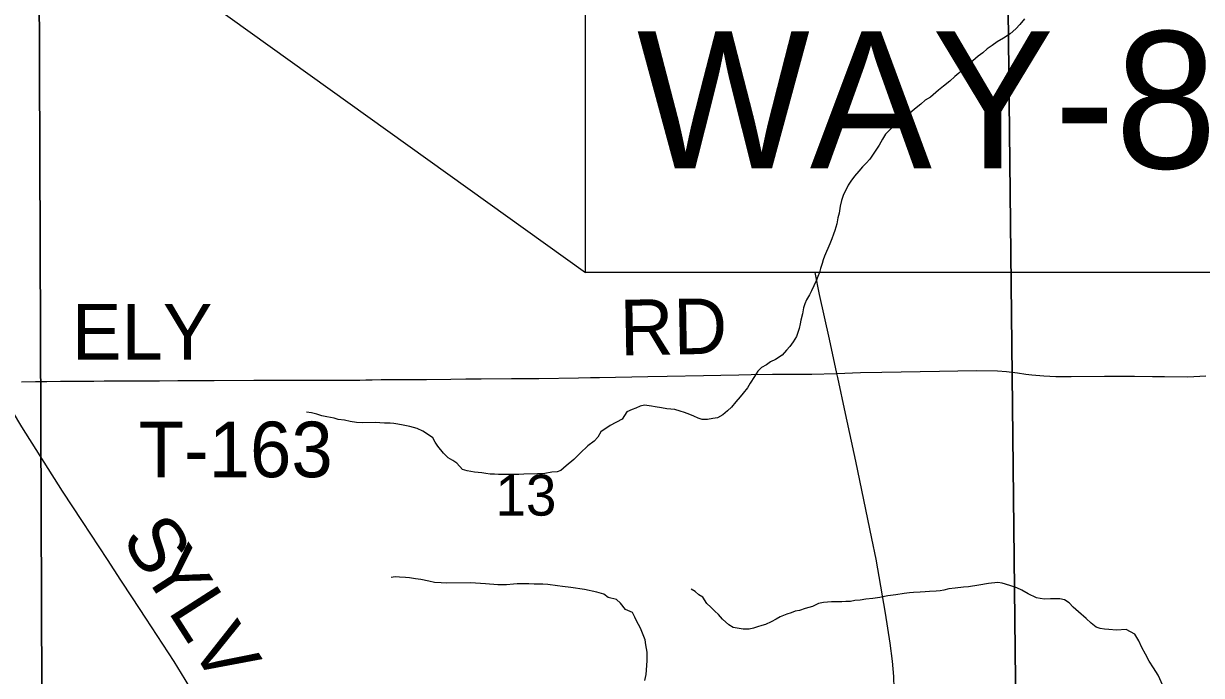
# Model space of a CAD drawing. Extents: x 0 to 34, y 0 to 22.
# Drawn here: x 22.282 to 23.486, y 11.815 to 12.481 of the extents above; entities that cross this region are included whole.
import ezdxf

# ---------------------------------------------------------------- set-up
doc = ezdxf.new("R2010")
doc.units = 0
for name, color, linetype in [('GM_X_County_Road', 7, 'Continuous'), ('GM_X_County_Road_Text', 7, 'Continuous'), ('GM_X_Minor_River', 7, 'Continuous'), ('GM_X_Section', 7, 'Continuous'), ('GM_X_Section_Text', 7, 'Continuous'), ('GM_X_Township_Road', 7, 'Continuous'), ('GM_X_Township_Road_Text', 7, 'Continuous'), ('SH_Text', 7, 'Continuous')]:
    doc.layers.add(name, color=color, linetype=linetype)

msp = doc.modelspace()

# ---------------------------------------------------------------- linework, layer by layer
at = {"layer": 'GM_X_County_Road'}
for points in [[(23.1137, 12.124), (23.106, 12.159), (23.096, 12.2046), (23.0913, 12.227)], [(22.5536, 11.616), (22.5355, 11.6502), (22.5139, 11.6915), (22.4919, 11.7326), (22.4757, 11.7627), (22.4634, 11.7843), (22.4475, 11.8111), (22.436, 11.8296), (22.4072, 11.8738), (22.3935, 11.8946), (22.3817, 11.9128), (22.3681, 11.9336), (22.3424, 11.9725), (22.3219, 12.0037), (22.2805, 12.0694), (22.2709, 12.0853), (22.2634, 12.0989), (22.2591, 12.1073), (22.2553, 12.1152)], [(23.1726, 11.6218), (23.1725, 11.6372), (23.1727, 11.69), (23.1722, 11.7304), (23.1721, 11.7677), (23.1722, 11.8019), (23.1717, 11.8143), (23.1704, 11.8297), (23.1681, 11.8482), (23.1633, 11.8789), (23.1585, 11.9065), (23.1536, 11.934), (23.1493, 11.9553), (23.1329, 12.0344), (23.1224, 12.0831), (23.1147, 12.1196), (23.1137, 12.124)]]:
    msp.add_lwpolyline(points, dxfattribs=at)
at = {"layer": 'GM_X_Minor_River'}
for points in [[(23.3053, 12.4863), (23.3008, 12.4806), (23.2967, 12.476), (23.2906, 12.471), (23.2839, 12.4667), (23.2774, 12.4628), (23.2722, 12.4589), (23.2673, 12.4555), (23.2628, 12.4516), (23.2579, 12.4481), (23.2526, 12.4435), (23.2481, 12.44), (23.2436, 12.4358), (23.2383, 12.4308), (23.2342, 12.4273), (23.2289, 12.4227), (23.2225, 12.4176), (23.2176, 12.4134), (23.2093, 12.4064), (23.204, 12.4033), (23.1995, 12.3991), (23.1931, 12.3941), (23.1879, 12.3894), (23.183, 12.3856), (23.1792, 12.3817), (23.1739, 12.3786), (23.1687, 12.374), (23.1634, 12.3686), (23.1601, 12.3632), (23.1567, 12.3571), (23.1508, 12.3479), (23.1474, 12.3429), (23.1437, 12.3387), (23.1399, 12.3349), (23.1362, 12.3306), (23.1317, 12.3256), (23.1279, 12.3203), (23.1253, 12.3164), (23.1201, 12.3057), (23.1183, 12.3008), (23.1168, 12.295), (23.1158, 12.2878), (23.1147, 12.2829), (23.1137, 12.2768), (23.1115, 12.2699), (23.11, 12.2661), (23.1085, 12.2615), (23.1063, 12.2562), (23.1011, 12.2439), (23.0997, 12.2401), (23.0986, 12.2363), (23.0967, 12.231), (23.0957, 12.2272), (23.0942, 12.223), (23.0923, 12.2184), (23.0901, 12.2134), (23.0875, 12.2084), (23.0857, 12.2042), (23.0827, 12.1992), (23.0809, 12.195), (23.0794, 12.1908), (23.0783, 12.1848), (23.0769, 12.1783), (23.0762, 12.1745), (23.0751, 12.1699), (23.0722, 12.1615), (23.0688, 12.1561), (23.0655, 12.1515), (23.0621, 12.1477), (23.0576, 12.1427), (23.0508, 12.138), (23.0459, 12.1357), (23.0417, 12.1326), (23.0364, 12.1299), (23.0327, 12.1264), (23.0293, 12.1207), (23.0249, 12.1141), (23.0223, 12.1092), (23.0178, 12.1038), (23.0148, 12.1), (23.0103, 12.095), (23.0058, 12.0896), (23.0017, 12.0857)], [(23.0017, 12.0857), (22.9971, 12.0815), (22.9915, 12.0784), (22.9869, 12.0779), (22.9812, 12.0767), (22.9759, 12.077), (22.9717, 12.0781), (22.9675, 12.0803), (22.9633, 12.0818), (22.9579, 12.084), (22.9534, 12.0855), (22.948, 12.0869), (22.9396, 12.0879), (22.9343, 12.0886), (22.9278, 12.0897), (22.924, 12.0904), (22.9171, 12.0914), (22.9126, 12.0906), (22.9081, 12.0883), (22.9043, 12.0871), (22.899, 12.0847), (22.8941, 12.0771), (22.882, 12.0708), (22.8722, 12.0643), (22.8693, 12.0589), (22.8655, 12.0547), (22.8591, 12.05), (22.8512, 12.0423), (22.8448, 12.0358), (22.8369, 12.0296), (22.8313, 12.0246), (22.8275, 12.0234), (22.8222, 12.0229), (22.815, 12.0217), (22.8074, 12.0212), (22.7937, 12.021), (22.7884, 12.0206), (22.78, 12.0205), (22.7716, 12.0207), (22.7678, 12.0207), (22.7636, 12.021), (22.7591, 12.021), (22.7549, 12.0217), (22.7507, 12.0224), (22.7431, 12.023), (22.7358, 12.0244), (22.7309, 12.0259), (22.7251, 12.0323), (22.7209, 12.0349), (22.7163, 12.0375), (22.7116, 12.0424), (22.7055, 12.0495), (22.7028, 12.0536), (22.7004, 12.0582), (22.695, 12.0619), (22.6904, 12.0649), (22.6847, 12.0675), (22.6771, 12.0696), (22.6702, 12.0711), (22.6649, 12.0721), (22.6607, 12.0728), (22.6569, 12.0732), (22.6512, 12.0731), (22.6462, 12.0734), (22.6416, 12.0737), (22.6287, 12.0735), (22.6226, 12.0738), (22.6161, 12.0749), (22.6104, 12.076), (22.6039, 12.077), (22.5997, 12.0781), (22.5921, 12.0795), (22.5872, 12.0806), (22.5818, 12.0824), (22.5765, 12.0835), (22.5715, 12.0842)], [(22.9174, 11.81), (22.9188, 11.8161), (22.9198, 11.8301), (22.9197, 11.8389), (22.9184, 11.8464), (22.9176, 11.8518), (22.9129, 11.8635), (22.9086, 11.871), (22.907, 11.8748), (22.9047, 11.8797), (22.8974, 11.8826), (22.8924, 11.889), (22.8882, 11.8928), (22.8798, 11.8949), (22.8752, 11.8983), (22.8683, 11.9005), (22.8557, 11.903), (22.8416, 11.9051), (22.8332, 11.9061), (22.8279, 11.9068), (22.818, 11.9082), (22.813, 11.9085), (22.8043, 11.9087), (22.7986, 11.909), (22.7868, 11.9089), (22.783, 11.9085), (22.7758, 11.908), (22.767, 11.9079), (22.7545, 11.9088), (22.7442, 11.9095), (22.7388, 11.9098), (22.7141, 11.9094), (22.7092, 11.9098), (22.7023, 11.9104), (22.6966, 11.9115), (22.6882, 11.9133), (22.6829, 11.914), (22.6768, 11.915), (22.6726, 11.9153), (22.6665, 11.9156), (22.6619, 11.916), (22.6581, 11.9155)], [(23.3993, 11.8616), (23.3917, 11.8622), (23.3871, 11.8626), (23.3826, 11.8633), (23.3787, 11.8647), (23.3734, 11.8688), (23.3684, 11.8733), (23.3607, 11.8801), (23.3553, 11.8849), (23.351, 11.8894), (23.3464, 11.8924), (23.3415, 11.8935), (23.3369, 11.8934), (23.332, 11.8937), (23.3259, 11.8933), (23.3213, 11.894), (23.3175, 11.8947), (23.3091, 11.8988), (23.3026, 11.9025), (23.2976, 11.9047), (23.2903, 11.9072), (23.2827, 11.9094), (23.2781, 11.9101), (23.2686, 11.9092), (23.2588, 11.9076), (23.2481, 11.9059), (23.2432, 11.9055), (23.2345, 11.9046), (23.228, 11.9038), (23.2231, 11.9025), (23.2193, 11.9017), (23.2151, 11.9013), (23.2083, 11.9012), (23.2037, 11.9008), (23.1988, 11.9003), (23.1919, 11.8999), (23.1878, 11.8998), (23.1824, 11.899), (23.1737, 11.8977), (23.1657, 11.8965), (23.1574, 11.8948), (23.1502, 11.894), (23.1433, 11.8931), (23.1373, 11.8923), (23.132, 11.8918), (23.1274, 11.891), (23.1228, 11.891), (23.1187, 11.8905), (23.108, 11.8904), (23.1, 11.8899), (23.0947, 11.8887), (23.0887, 11.8856), (23.0811, 11.8836), (23.0754, 11.8816), (23.0709, 11.8808), (23.0667, 11.8792), (23.0625, 11.878), (23.0557, 11.8752), (23.0516, 11.8729), (23.0463, 11.8702), (23.0406, 11.8674), (23.0368, 11.8663), (23.0323, 11.8651), (23.0285, 11.8635), (23.0239, 11.8627), (23.0179, 11.8626), (23.0137, 11.8633), (23.0076, 11.8644), (23.003, 11.8669), (22.9968, 11.8729), (22.9926, 11.8774), (22.9887, 11.8808), (22.9849, 11.8849), (22.9806, 11.8887), (22.9767, 11.8951), (22.9725, 11.8977), (22.9687, 11.9011), (22.9648, 11.9033)], [(23.4467, 11.8051), (23.4421, 11.8157), (23.4374, 11.8229), (23.4328, 11.8297), (23.429, 11.8369), (23.4255, 11.8437), (23.4224, 11.8505), (23.4181, 11.8574), (23.4094, 11.8621), (23.3993, 11.8616)]]:
    msp.add_lwpolyline(points, dxfattribs=at)
at = {"layer": 'GM_X_Section'}
for points in [[(23.2871, 12.632), (23.2872, 12.6207), (23.2983, 11.6235), (22.3015, 11.617), (22.2979, 12.6206)], [(21.3125, 12.6129), (22.2979, 12.6206), (22.3015, 11.617), (21.2987, 11.6032), (21.3118, 11.9349)], [(23.2872, 12.6207), (23.9982, 12.6247), (24.0077, 11.623), (23.2983, 11.6235)]]:
    msp.add_lwpolyline(points, close=True, dxfattribs=at)
at = {"layer": 'GM_X_Township_Road'}
for points in [[(23.1137, 12.124), (23.1378, 12.1247), (23.1595, 12.1253), (23.2186, 12.1261), (23.2559, 12.1269), (23.2777, 12.1265), (23.287, 12.1259), (23.2984, 12.1244)], [(22.2801, 12.1155), (22.2942, 12.1157), (22.3059, 12.1158), (22.3198, 12.116), (22.3291, 12.116), (22.3358, 12.1161), (22.3437, 12.1161), (22.354, 12.1161), (22.3644, 12.1162), (22.384, 12.1163), (22.3932, 12.1162), (22.4025, 12.1162), (22.4211, 12.1165), (22.4398, 12.1166), (22.4771, 12.1168), (22.5174, 12.117), (22.536, 12.1171), (22.5733, 12.1169), (22.595, 12.117), (22.6074, 12.117), (22.626, 12.1172), (22.6322, 12.1173), (22.6384, 12.1175), (22.6477, 12.1176), (22.657, 12.1177), (22.6663, 12.1177), (22.6818, 12.1178), (22.688, 12.1178), (22.6942, 12.1177), (22.7189, 12.1181), (22.7344, 12.1183), (22.75, 12.1183), (22.781, 12.1186), (22.809, 12.1189), (22.8494, 12.1193), (22.8618, 12.1196), (22.871, 12.1199), (22.9203, 12.1208), (22.9402, 12.1212), (22.9773, 12.1219), (22.9951, 12.1222), (23.0135, 12.1224), (23.0259, 12.1227), (23.0477, 12.1231), (23.0664, 12.1233), (23.0881, 12.1233), (23.1129, 12.124), (23.1137, 12.124)], [(23.2984, 12.1244), (23.3068, 12.1232), (23.3129, 12.1226), (23.3253, 12.1215), (23.3376, 12.1209), (23.3531, 12.1208), (23.3873, 12.1212), (23.4059, 12.1212), (23.418, 12.1211), (23.4362, 12.1209), (23.4485, 12.1207), (23.4725, 12.1206), (23.4907, 12.1213)]]:
    msp.add_lwpolyline(points, dxfattribs=at)
at = {"layer": 'SH_Text'}
for points in [[(22.8565, 12.5686), (21.3852, 13.2813), (22.8565, 12.227)], [(22.8565, 12.5686), (24.2225, 12.5686), (24.2225, 12.227), (22.8565, 12.227)]]:
    msp.add_lwpolyline(points, close=True, dxfattribs=at)

# ---------------------------------------------------------------- texts
at = {"layer": 'GM_X_County_Road_Text'}
for s, rotation, p in [('S', 302.8427, (22.3813, 11.9552)), ('Y', 302.8424, (22.402, 11.923)), ('L', 302.6512, (22.4291, 11.8811)), ('V', 301.2343, (22.4519, 11.8456))]:
    msp.add_text(s, height=0.0568, rotation=rotation, dxfattribs=at).set_placement(p)
at = {"layer": 'GM_X_Section_Text'}
msp.add_text('13', height=0.04186, rotation=0, dxfattribs=at).set_placement((22.7646, 11.9786))
at = {"layer": 'GM_X_Township_Road_Text'}
for s, rotation, p in [('RD', 0.987, (22.8921, 12.1423)), ('ELY', 0, (22.3316, 12.1381)), ('T-163', 0.0064, (22.3997, 12.0178))]:
    msp.add_text(s, height=0.05682, rotation=rotation, dxfattribs=at).set_placement(p)
at = {"layer": 'SH_Text'}
msp.add_text('WAY-83-10.73', height=0.14, dxfattribs=at).set_placement((22.9092, 12.3335))

doc.saveas('drawing.dxf')
